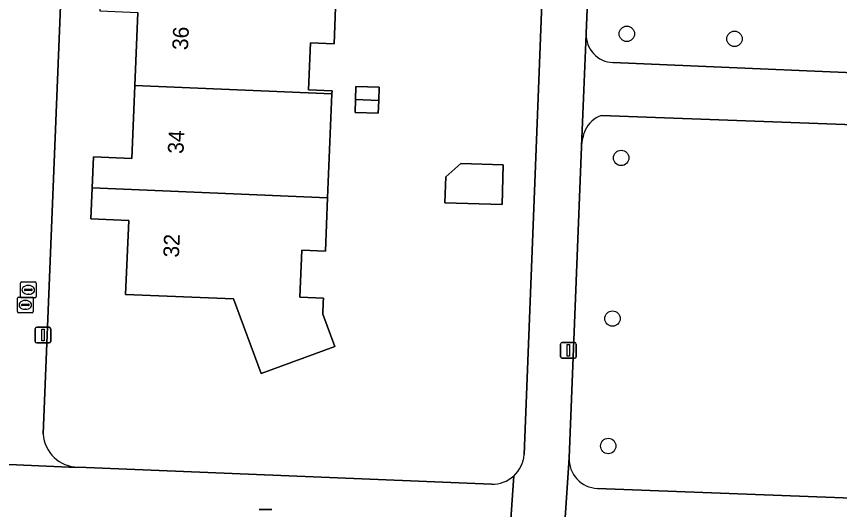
# Model space of a CAD drawing. Extents: x 160786 to 161429, y 386828 to 387485.
# Drawn here: x 161086.3 to 161138.7, y 386933.6 to 386964.9 of the extents above; entities that cross this region are included whole.
import ezdxf

# ---------------------------------------------------------------- set-up
doc = ezdxf.new("R2010")
doc.units = 0
for name, color, linetype in [('IMGEO_Boom', 7, 'Continuous'), ('IMGEO_Brandkraan', 7, 'Continuous'), ('IMGEO_Erf', 7, 'Continuous'), ('IMGEO_Groenvoorziening', 7, 'Continuous'), ('IMGEO_Kolk', 7, 'Continuous'), ('IMGEO_Lichtmast', 7, 'Continuous'), ('IMGEO_Pand', 7, 'Continuous'), ('IMGEO_Pand_nummerreeks', 7, 'Continuous'), ('IMGEO_Voetpad_open', 7, 'Continuous')]:
    doc.layers.add(name, color=color, linetype=linetype)

msp = doc.modelspace()

# ---------------------------------------------------------------- linework, layer by layer
at = {"layer": 'IMGEO_Boom'}
for centre in [(161125.14, 386963.837), (161131.983, 386963.518), (161124.779, 386955.953), (161124.226, 386945.747), (161123.956, 386937.651)]:
    msp.add_circle(centre, 0.489, dxfattribs=at)
at = {"layer": 'IMGEO_Brandkraan'}
for p, q in [((161086.404, 386946.189), (161086.404, 386947.041)), ((161086.479, 386947.115), (161087.331, 386947.115)), ((161086.892, 386946.895), (161086.917, 386946.895)), ((161087.405, 386947.041), (161087.405, 386946.189)), ((161086.663, 386946.609), (161086.663, 386946.621)), ((161087.101, 386946.572), (161086.703, 386946.572)), ((161086.706, 386946.658), (161087.104, 386946.658)), ((161086.915, 386946.335), (161086.89, 386946.335)), ((161087.147, 386946.621), (161087.147, 386946.609)), ((161087.331, 386946.115), (161086.479, 386946.115))]:
    msp.add_line(p, q, dxfattribs=at)
for points in [[(161086.404, 386946.189), (161086.404, 386947.041)], [(161086.479, 386947.115), (161087.331, 386947.115)], [(161087.405, 386947.041), (161087.405, 386946.189)], [(161087.331, 386946.115), (161086.479, 386946.115)]]:
    msp.add_lwpolyline(points, dxfattribs=at)
for centre, radius, start, end in [((161086.481, 386947.039), 0.0765, 91.552, 178.448), ((161086.481, 386947.039), 0.0765, 91.552, 178.448), ((161087.329, 386947.039), 0.0765, 1.552, 88.448), ((161087.329, 386947.039), 0.0765, 1.552, 88.448), ((161086.703, 386946.618), 0.0403, 85.8775, 175.7526), ((161086.7, 386946.608), 0.0366, 178.938, 274.7102), ((161087.104, 386946.615), 0.043, 264.8664, 352.4533), ((161087.108, 386946.62), 0.0386, 1.7309, 96.639), ((161086.481, 386946.191), 0.0765, 181.552, 268.448), ((161086.481, 386946.191), 0.0765, 181.552, 268.448), ((161087.329, 386946.191), 0.0765, 271.552, 358.448), ((161087.329, 386946.191), 0.0765, 271.552, 358.448)]:
    msp.add_arc(centre, radius, start, end, dxfattribs=at)
for centre, major_axis, ratio, start_param, end_param in [((161086.891, 386946.615), (-0.387, 0.002), 0.722429, 4.712389, 7.853982), ((161086.916, 386946.615), (-0.39, 0.002), 0.717154, 1.570796, 4.712389)]:
    msp.add_ellipse(centre, major_axis=major_axis, ratio=ratio, start_param=start_param, end_param=end_param, dxfattribs=at)
at = {"layer": 'IMGEO_Erf'}
for points in [[(161119.475, 386959.244), (161121.076, 387000)], [(161090.045, 386988.116), (161088.04, 386938.415)], [(161106.672, 386966.677), (161106.528, 386963.209), (161105.029, 386963.271), (161104.905, 386960.274), (161106.403, 386960.212), (161106.396, 386960.032), (161106.121, 386953.426), (161105.98, 386950.035), (161104.481, 386950.097), (161104.357, 386947.099), (161105.856, 386947.038), (161105.845, 386946.768), (161105.815, 386946.036), (161106.574, 386943.978), (161101.892, 386942.251), (161100.139, 386947.003), (161093.282, 386947.285), (161093.476, 386951.978), (161091.071, 386952.077), (161091.153, 386954.048), (161091.234, 386956.018), (161093.683, 386955.917), (161093.874, 386960.552), (161094.065, 386965.19)], [(161118.604, 386937.102), (161119.475, 386959.244)], [(161090.255, 386936.31), (161116.527, 386935.233)]]:
    msp.add_lwpolyline(points, dxfattribs=at)
for points in [[(161107.86, 386958.842), (161107.889, 386959.656), (161107.918, 386960.491), (161109.396, 386960.439), (161109.367, 386959.604), (161109.339, 386958.79)], [(161113.625, 386954.759), (161114.588, 386955.605), (161117.284, 386955.521), (161117.205, 386952.988), (161113.574, 386953.101)]]:
    msp.add_lwpolyline(points, close=True, dxfattribs=at)
for centre, radius, start, end in [((161090.29, 386938.565), 2.255, 183.8188, 269.0984), ((161116.611, 386937.23), 1.997, 311.9499, 356.3132), ((161116.609, 386937.229), 1.997, 267.654, 312.0267)]:
    msp.add_arc(centre, radius, start, end, dxfattribs=at)
at = {"layer": 'IMGEO_Groenvoorziening'}
for points in [[(161126.838, 387069.748), (161124.044, 387000), (161122.553, 386963.852)], [(161124.256, 386962.014), (161145.968, 386961.082)], [(161145.823, 386957.811), (161145.293, 386957.851), (161144.741, 386957.868), (161123.522, 386958.645)], [(161122.253, 386956.657), (161121.473, 386936.897)], [(161123.268, 386934.957), (161145.036, 386934.128)]]:
    msp.add_lwpolyline(points, dxfattribs=at)
for centre, radius, start, end in [((161124.323, 386963.784), 1.772, 177.8102, 267.8231), ((161124.039, 386957.033), 1.693, 107.7634, 156.4915), ((161125.375, 386956.516), 3.125, 157.5831, 177.4171), ((161123.339, 386936.823), 1.867, 177.7258, 267.8277)]:
    msp.add_arc(centre, radius, start, end, dxfattribs=at)
at = {"layer": 'IMGEO_Kolk'}
for p, q in [((161086.591, 386947.146), (161086.591, 386947.998)), ((161086.666, 386948.072), (161087.518, 386948.072)), ((161087.079, 386947.852), (161087.104, 386947.852)), ((161087.592, 386947.998), (161087.592, 386947.146)), ((161086.85, 386947.566), (161086.85, 386947.578)), ((161087.288, 386947.529), (161086.89, 386947.529)), ((161086.893, 386947.615), (161087.291, 386947.615)), ((161087.334, 386947.578), (161087.334, 386947.566)), ((161087.518, 386947.072), (161086.666, 386947.072)), ((161087.102, 386947.292), (161087.077, 386947.292))]:
    msp.add_line(p, q, dxfattribs=at)
for points in [[(161086.591, 386947.146), (161086.591, 386947.998)], [(161086.666, 386948.072), (161087.518, 386948.072)], [(161087.592, 386947.998), (161087.592, 386947.146)], [(161087.518, 386947.072), (161086.666, 386947.072)]]:
    msp.add_lwpolyline(points, dxfattribs=at)
for centre, radius, start, end in [((161086.668, 386947.996), 0.0765, 91.552, 178.448), ((161086.668, 386947.996), 0.0765, 91.552, 178.448), ((161087.516, 386947.996), 0.0765, 1.552, 88.448), ((161087.516, 386947.996), 0.0765, 1.552, 88.448), ((161086.89, 386947.575), 0.0403, 85.8775, 175.7526), ((161086.887, 386947.565), 0.0366, 178.938, 274.7102), ((161087.291, 386947.572), 0.043, 264.8664, 352.4533), ((161087.295, 386947.577), 0.0386, 1.7309, 96.639), ((161086.668, 386947.148), 0.0765, 181.552, 268.448), ((161086.668, 386947.148), 0.0765, 181.552, 268.448), ((161087.516, 386947.148), 0.0765, 271.552, 358.448), ((161087.516, 386947.148), 0.0765, 271.552, 358.448)]:
    msp.add_arc(centre, radius, start, end, dxfattribs=at)
for centre, major_axis, ratio, start_param, end_param in [((161087.078, 386947.572), (-0.387, 0.002), 0.722429, 4.712389, 7.853982), ((161087.103, 386947.572), (-0.39, 0.002), 0.717154, 1.570796, 4.712389)]:
    msp.add_ellipse(centre, major_axis=major_axis, ratio=ratio, start_param=start_param, end_param=end_param, dxfattribs=at)
at = {"layer": 'IMGEO_Lichtmast'}
for p, q in [((161087.527, 386944.298), (161087.527, 386945.098)), ((161087.527, 386945.098), (161087.527, 386944.298)), ((161087.627, 386945.198), (161088.417, 386945.198)), ((161088.417, 386945.198), (161087.627, 386945.198)), ((161088.517, 386945.098), (161088.517, 386944.298)), ((161088.517, 386944.298), (161088.517, 386945.098)), ((161088.417, 386944.198), (161087.627, 386944.198)), ((161087.627, 386944.198), (161088.417, 386944.198)), ((161121.029, 386944.226), (161121.819, 386944.226)), ((161121.819, 386944.226), (161121.029, 386944.226)), ((161120.929, 386943.326), (161120.929, 386944.126)), ((161120.929, 386944.126), (161120.929, 386943.326)), ((161121.919, 386944.126), (161121.919, 386943.326)), ((161121.919, 386943.326), (161121.919, 386944.126)), ((161121.819, 386943.226), (161121.029, 386943.226)), ((161121.029, 386943.226), (161121.819, 386943.226)), ((161101.777, 386933.615), (161102.567, 386933.615)), ((161102.567, 386933.615), (161101.777, 386933.615))]:
    msp.add_line(p, q, dxfattribs=at)
for points in [[(161087.947, 386945.073), (161088.097, 386945.073), (161088.097, 386944.323), (161087.947, 386944.323), (161087.947, 386945.073)], [(161121.349, 386944.101), (161121.499, 386944.101), (161121.499, 386943.351), (161121.349, 386943.351), (161121.349, 386944.101)]]:
    msp.add_lwpolyline(points, dxfattribs=at)
for centre, start, end in [((161087.627, 386945.098), 90, 180), ((161087.627, 386945.098), 90, 180), ((161088.417, 386945.098), 0, 90), ((161088.417, 386945.098), 360, 90), ((161087.627, 386944.298), 180, 270), ((161087.627, 386944.298), 180, 270), ((161088.417, 386944.298), 270, 0), ((161088.417, 386944.298), 270, 0), ((161121.029, 386944.126), 90, 180), ((161121.029, 386944.126), 90, 180), ((161121.819, 386944.126), 0, 90), ((161121.819, 386944.126), 360, 90), ((161121.029, 386943.326), 180, 270), ((161121.029, 386943.326), 180, 270), ((161121.819, 386943.326), 270, 0), ((161121.819, 386943.326), 270, 0)]:
    msp.add_arc(centre, 0.1, start, end, dxfattribs=at)
at = {"layer": 'IMGEO_Pand'}
for points in [[(161106.672, 386966.677), (161091.722, 386967.298), (161091.639, 386965.29), (161094.065, 386965.19), (161093.874, 386960.552), (161106.396, 386960.032), (161106.403, 386960.212), (161104.905, 386960.274), (161105.029, 386963.271), (161106.528, 386963.209)], [(161106.121, 386953.426), (161106.396, 386960.032), (161093.874, 386960.552), (161093.683, 386955.917), (161091.234, 386956.018), (161091.153, 386954.048)], [(161107.889, 386959.656), (161109.367, 386959.604), (161109.396, 386960.439), (161107.918, 386960.491)], [(161109.367, 386959.604), (161107.889, 386959.656), (161107.86, 386958.842), (161109.339, 386958.79)], [(161114.588, 386955.605), (161113.625, 386954.759), (161113.574, 386953.101), (161117.205, 386952.988), (161117.284, 386955.521)], [(161104.481, 386950.097), (161105.98, 386950.035), (161106.121, 386953.426), (161091.153, 386954.048), (161091.071, 386952.077), (161093.476, 386951.978), (161093.282, 386947.285), (161100.139, 386947.003), (161101.892, 386942.251), (161106.574, 386943.978), (161105.815, 386946.036), (161105.845, 386946.768), (161105.856, 386947.038), (161104.357, 386947.099)]]:
    msp.add_lwpolyline(points, close=True, dxfattribs=at)
at = {"layer": 'IMGEO_Voetpad_open'}
for points in [[(161128.864, 387071.378), (161129.056, 387074.52), (161124.099, 387074.719), (161123.098, 387049.797), (161123.092, 387049.703), (161122.751, 387042.869), (161122.753, 387042.692), (161122.596, 387038.706), (161121.076, 387000), (161119.475, 386959.244), (161118.604, 386937.102)], [(161120.37, 386911.783), (161120.564, 386917.225), (161120.797, 386923.755), (161120.97, 386928.628), (161121.017, 386929.934), (161121.473, 386936.897), (161122.253, 386956.657), (161122.251, 386956.693), (161122.549, 386963.816), (161122.553, 386963.852), (161124.044, 387000), (161126.838, 387069.748)], [(161088.04, 386938.415), (161090.045, 386988.116), (161090.524, 387000)], [(161122.553, 386963.852), (161122.549, 386963.816), (161122.251, 386956.693), (161122.253, 386956.657)], [(161145.968, 386961.082), (161124.256, 386962.014)], [(161123.522, 386958.645), (161144.741, 386957.868), (161145.293, 386957.851), (161145.823, 386957.811)], [(161090.255, 386936.31), (161090.15, 386936.295), (161082.967, 386936.595), (161082.88, 386936.613), (161038.862, 386938.273), (161038.808, 386938.265), (161031.942, 386938.539), (161031.883, 386938.55), (161000, 386939.854), (160991.5, 386940.197), (160991.347, 386935.625)], [(161121.473, 386936.897), (161121.017, 386929.934)], [(161082.88, 386936.613), (161082.967, 386936.595), (161090.15, 386936.295), (161090.255, 386936.31)], [(161116.527, 386935.233), (161090.255, 386936.31)], [(161117.632, 386931.131), (161117.946, 386935.745)], [(161117.946, 386935.745), (161117.632, 386931.131)], [(161145.036, 386934.128), (161123.268, 386934.957)]]:
    msp.add_lwpolyline(points, dxfattribs=at)
for centre, radius, start, end in [((161124.323, 386963.784), 1.772, 177.8102, 267.8231), ((161124.039, 386957.033), 1.693, 107.7634, 156.4915), ((161125.375, 386956.516), 3.125, 157.5831, 177.4171), ((161090.29, 386938.565), 2.255, 183.8188, 269.0984), ((161116.611, 386937.23), 1.997, 311.9499, 356.3132), ((161123.339, 386936.823), 1.867, 177.7258, 267.8277), ((161116.609, 386937.229), 1.997, 267.654, 312.0267)]:
    msp.add_arc(centre, radius, start, end, dxfattribs=at)

# ---------------------------------------------------------------- texts
at = {"layer": 'IMGEO_Pand_nummerreeks'}
for s, rotation, p in [('36', 87.5021, (161097.241, 386962.787)), ('34', 87.5008, (161096.954, 386956.199)), ('32', 87.5021, (161096.666, 386949.608))]:
    msp.add_text(s, height=1, rotation=rotation, dxfattribs=at).set_placement(p)

doc.saveas('drawing.dxf')
